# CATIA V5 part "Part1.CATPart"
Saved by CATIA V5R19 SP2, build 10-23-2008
Part number: Test
Bounding box of the stored display mesh (mm): x -30 to 30, y -30 to 30, z 0 to 10
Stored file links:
  C:\Dokumente und Einstellungen\Rolf\Desktop\CATIA-V5-Test\Part1.CATPart
  C:\Programme\Dassault Systemes\B19\intel_a\reffiles\standard\MetricThickPitch.txt
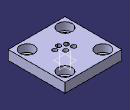
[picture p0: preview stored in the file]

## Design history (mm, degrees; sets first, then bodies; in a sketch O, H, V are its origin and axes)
TTRSSet1
Body1 (main body)
  Sketch1 on xy-plane, origin (0, 0, 0), H (1, 0, 0), V (0, 1, 0)
    line L1 (-30, -30) -> (30, -30)
    line L2 (30, -30) -> (30, 30)
    line L3 (30, 30) -> (-30, 30)
    line L4 (-30, 30) -> (-30, -30)
    construction line L5 (0, 0) -> (30, 0)
    axis line L6 (0, 0) -> (0, 20)
    distance L5 L3 = 30
    length L3 = 60
    distance L2 L6 = 30
    length L4 = 60
    horizontal: L1 H, L3 H, L5 H
    vertical: L2 V, L4 V, L6 V
  Pad1: profile Sketch1, direction (0, 0, 1), length 10
  Sketch2 on end face of Pad1, origin (-11.6017, -4.6121, 10), H (1, 0, 0), V (0, 1, 0)
    point P1 (-8.3983, -15.3879)
    reference projected line E1 (-8.3983, -25.3879) -> (31.6017, -25.3879) from edge [face of Pad1 from Sketch1.L1 | end face of Pad1]
    point P2 (-8.3983, -15.3879)
    point P3 (-8.3983, -15.3879)
    distance P1 E1 = 10
  Hole1: placed by Sketch2, at (-20, -20, 10) direction (0, 0, -1), diameter 10, through (limit type 6), counterbore diameter 15, counterbore depth 8
  RectPattern1: of Hole1, direction 1 instances 2, spacing 40, along end face of Pad1, direction 2 instances 2, spacing 40, along end face of Pad1
  Sketch3 on end face of Pad1, origin (0.5289, 1.2027, 10), H (1, 0, 0), V (0, 1, 0)
    point P1 (0, 0)
  Hole2: placed by Sketch3, at (0.5289, 1.2027, 10) direction (0, 0, -1), diameter 4.917, through (limit type 6), threaded "M6", thread diameter 6, thread depth 10, pitch 1
  Sketch4 on end face of Pad1, origin (-7.5533, 1.7737, 10), H (1, 0, 0), V (0, 1, 0)
    point P1 (0, 0)
  Hole3: placed by Sketch4, at (-7.5533, 1.7737, 10) direction (0, 0, -1), diameter 4.917, through (limit type 6), threaded "M6", thread diameter 6, thread depth 10, pitch 1
  CircPattern1: of Hole3, instances 4, angular step 45, axis from face of Hole2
